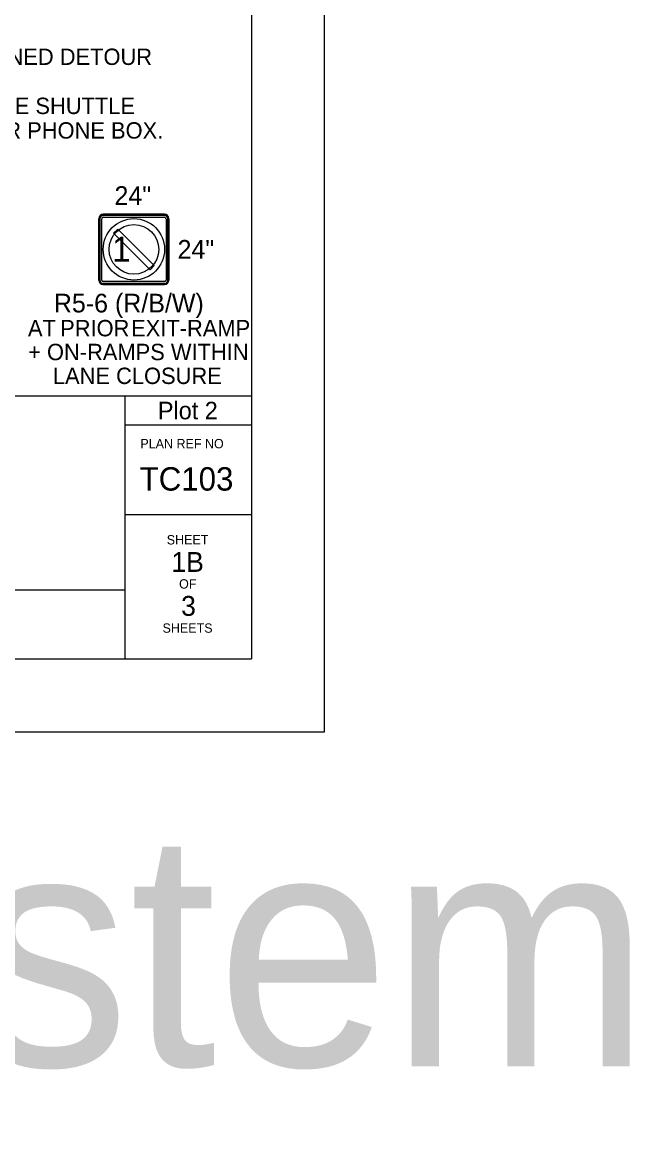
# Model space of a CAD drawing. Extents: x 99999 to 100116, y 99995 to 100013.
# Drawn here: x 100034.769 to 100037.37, y 99997.956 to 100002.723 of the extents above; entities that cross this region are included whole.
import ezdxf

# ---------------------------------------------------------------- set-up
doc = ezdxf.new("R2010")
doc.units = 0
for name, color, linetype in [('SH_GI_GeneralNotesBodyText', 7, 'Continuous'), ('SH_GI_PlotLimits', 7, 'Continuous'), ('SH_GI_SheetBorder', 7, 'Continuous'), ('SH_GI_SheetLocationText', 7, 'Continuous'), ('SH_GI_SheetTextInCells', 7, 'Continuous'), ('SH_GI_TitleBlockText', 7, 'Continuous'), ('TR_SN_ConstructionSigns', 7, 'Continuous')]:
    doc.layers.add(name, color=color, linetype=linetype)

msp = doc.modelspace()

# ---------------------------------------------------------------- linework, layer by layer
at = {"layer": 'SH_GI_PlotLimits'}
msp.add_lwpolyline([(100019.0625, 99999.6875), (100036.0625, 99999.6875), (100036.0625, 100010.6875), (100019.0625, 100010.6875)], close=True, dxfattribs=at)
at = {"layer": 'SH_GI_SheetBorder'}
for p, q in [((100035.75, 100010.375), (100035.75, 100000)), ((100020, 100001.1259), (100035.75, 100001.1259)), ((100035.2079, 100001.1259), (100035.2079, 100000)), ((100035.2079, 100001.0008), (100035.75, 100001.0008)), ((100035.2079, 100000.6176), (100035.75, 100000.6176)), ((100032.2055, 100000.2955), (100035.2079, 100000.2955)), ((100020, 100000), (100035.75, 100000))]:
    msp.add_line(p, q, dxfattribs=at)
at = {"layer": 'TR_SN_ConstructionSigns'}
for p, q in [((100035.0971, 100001.8831), (100035.0971, 100001.6206)), ((100035.0971, 100001.6206), (100035.0971, 100001.8831)), ((100035.0971, 100001.8831), (100035.0971, 100001.6206)), ((100035.1018, 100001.8831), (100035.1018, 100001.6206)), ((100035.1096, 100001.6206), (100035.1096, 100001.8831)), ((100035.3783, 100001.9019), (100035.1158, 100001.9019)), ((100035.1158, 100001.9019), (100035.3783, 100001.9019)), ((100035.3783, 100001.9019), (100035.1158, 100001.9019)), ((100035.3783, 100001.8972), (100035.1158, 100001.8972)), ((100035.1158, 100001.8894), (100035.3783, 100001.8894)), ((100035.3846, 100001.8831), (100035.3846, 100001.6206)), ((100035.3924, 100001.6206), (100035.3924, 100001.8831)), ((100035.3971, 100001.6206), (100035.3971, 100001.8831)), ((100035.3971, 100001.8831), (100035.3971, 100001.6206)), ((100035.3971, 100001.6206), (100035.3971, 100001.8831)), ((100035.3783, 100001.6144), (100035.1158, 100001.6144)), ((100035.1158, 100001.6066), (100035.3783, 100001.6066)), ((100035.1158, 100001.6019), (100035.3783, 100001.6019)), ((100035.3783, 100001.6019), (100035.1158, 100001.6019)), ((100035.1158, 100001.6019), (100035.3783, 100001.6019))]:
    msp.add_line(p, q, dxfattribs=at)
msp.add_lwpolyline([(100035.3305, 100001.6861), (100035.1813, 100001.8353), (100035.1778, 100001.8389), (100035.1601, 100001.8212), (100035.3128, 100001.6685), (100035.3164, 100001.6649), (100035.3341, 100001.6826), (100035.3305, 100001.6861)], dxfattribs=at)
for radius in [0.1313, 0.1062]:
    msp.add_circle((100035.2471, 100001.7519), radius, dxfattribs=at)
for centre, radius, start, end in [((100035.1158, 100001.8831), 0.0187, 90, 180), ((100035.1158, 100001.8831), 0.0187, 90, 180), ((100035.1158, 100001.8831), 0.0187, 90, 180), ((100035.1158, 100001.8831), 0.0141, 90, 180), ((100035.1158, 100001.8831), 0.00625, 90, 180), ((100035.3783, 100001.8831), 0.0187, 0, 90), ((100035.3783, 100001.8831), 0.0187, 0, 90), ((100035.3783, 100001.8831), 0.0187, 0, 90), ((100035.3783, 100001.8831), 0.0141, 0, 90), ((100035.3783, 100001.8831), 0.00625, 0, 90), ((100035.1158, 100001.6206), 0.0187, 180, 270), ((100035.1158, 100001.6206), 0.0187, 180, 270), ((100035.1158, 100001.6206), 0.0187, 180, 270), ((100035.1158, 100001.6206), 0.0141, 180, 270), ((100035.1158, 100001.6206), 0.00625, 180, 270), ((100035.3783, 100001.6206), 0.0141, 270, 0), ((100035.3783, 100001.6206), 0.00625, 270, 0), ((100035.3783, 100001.6206), 0.0187, 270, 0), ((100035.3783, 100001.6206), 0.0187, 270, 0), ((100035.3783, 100001.6206), 0.0187, 270, 0)]:
    msp.add_arc(centre, radius, start, end, dxfattribs=at)

# ---------------------------------------------------------------- texts
at = {"layer": 'SH_GI_GeneralNotesBodyText'}
for s, p in [('(B) BICYCLES PROHIBITED VIA R5-601 & R5-6 SIGNS. PROVIDE SIGNED DETOUR ', (100031.689, 100002.5406)), ('(C) BICYCLES PROHIBITED VIA R5-601 & R5-6 SIGNS. PROVIDE FREE SHUTTLE ', (100031.689, 100002.3306)), ('(WORK TRUCK, VAN, OR BUS OK) + CONTACT INFORMATION OR PHONE BOX.', (100031.839, 100002.2256))]:
    msp.add_text(s, height=0.07, rotation=360, dxfattribs=at).set_placement(p)
at = {"layer": 'SH_GI_SheetBorder'}
msp.add_text('PLAN REF NO', height=0.040032, dxfattribs=at).set_placement((100035.2747, 100000.9008))
at = {"layer": 'SH_GI_SheetLocationText'}
for s, height, p in [('Plot 2', 0.075, (100035.3497, 100001.025)), ('3-Mile Queue Warning System', 1, (100019.2499, 99998.258))]:
    msp.add_text(s, height=height, dxfattribs=at).set_placement(p)
at = {"layer": 'SH_GI_SheetTextInCells'}
for s, p in [('SHEET', (100035.3877, 100000.4896)), ('OF', (100035.4406, 100000.3008)), ('SHEETS', (100035.3698, 100000.112))]:
    msp.add_text(s, height=0.04003, dxfattribs=at).set_placement(p)
at = {"layer": 'SH_GI_TitleBlockText'}
for s, height, p in [('TC103', 0.1, (100035.2718, 100000.72)), ('1B', 0.085, (100035.4076, 100000.3723)), ('3', 0.085, (100035.4493, 100000.1843))]:
    msp.add_text(s, height=height, dxfattribs=at).set_placement(p)
at = {"layer": 'TR_SN_ConstructionSigns'}
for s, height, p in [('24"', 0.08, (100035.164, 100001.9419)), ('24"', 0.08, (100035.434, 100001.7119)), ('R5-6 (R/B/W)', 0.08, (100034.9045, 100001.4819)), ('AT', 0.07, (100034.7937, 100001.3799)), ('PRIOR', 0.07, (100034.9314, 100001.3799)), ('EXIT-RAMP', 0.07, (100035.2353, 100001.3799)), ('+ ON-RAMPS WITHIN', 0.07, (100034.7944, 100001.2779)), ('LANE CLOSURE', 0.07, (100034.9003, 100001.1759))]:
    msp.add_text(s, height=height, rotation=360, dxfattribs=at).set_placement(p)
msp.add_text('1', height=0.1065, dxfattribs=at).set_placement((100035.1538, 100001.6994))

doc.saveas('drawing.dxf')
